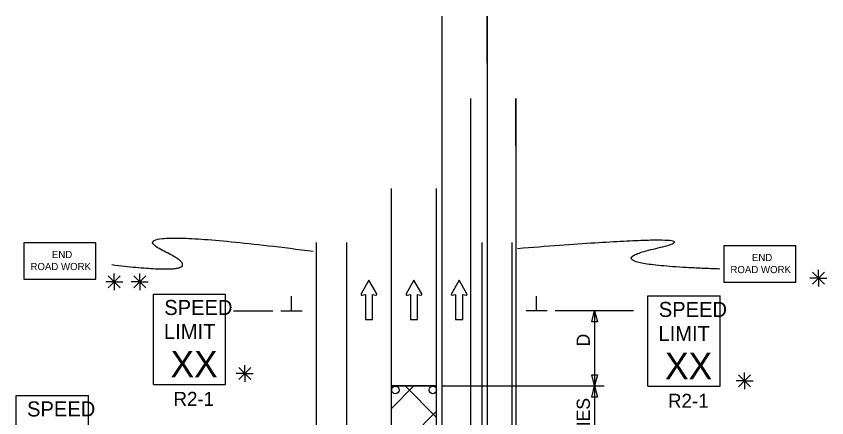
# Model space of a CAD drawing. Extents: x 16480 to 18482, y 7002 to 8333.
# Drawn here: x 16754.4 to 17185.3, y 8119.6 to 8333.1 of the extents above; entities that cross this region are included whole.
import ezdxf

# ---------------------------------------------------------------- set-up
doc = ezdxf.new("R2010")
doc.units = 0
for name, color, linetype in [('ALI_LEGAL_EX', 7, 'Continuous'), ('MT_SCRATCH_LEVEL_E', 7, 'Continuous'), ('PAVT_EDGE_EX', 7, 'Continuous'), ('TRAFFIC_SIGNS_PR', 7, 'Continuous'), ('TYPICAL_TEXT_DIMEN_PR', 7, 'Continuous')]:
    doc.layers.add(name, color=color, linetype=linetype)

msp = doc.modelspace()

# ---------------------------------------------------------------- linework, layer by layer
at = {"layer": 'ALI_LEGAL_EX'}
for p, q in [((16980.68, 8333.08), (16980.68, 7514.94)), ((17004.68, 8333.08), (17004.68, 7514.94)), ((16995.95, 8289.26), (16995.95, 7471.12)), ((17019.95, 8289.26), (17019.95, 7471.12)), ((16953.87, 7620.35), (16953.87, 8241.48)), ((16977.87, 7620.35), (16977.87, 8241.48))]:
    msp.add_line(p, q, dxfattribs=at)
for points in [[(17004.68, 8308.08), (17004.68, 8333.08)], [(17019.95, 8264.26), (17019.95, 8289.26)], [(16953.87, 8175.35), (16953.87, 8200.34)], [(16977.87, 8175.35), (16977.87, 8200.34)]]:
    msp.add_lwpolyline(points, dxfattribs=at)
at = {"layer": 'MT_SCRATCH_LEVEL_E'}
for p, q in [((16941.87, 8192.71), (16937.75, 8185.47)), ((16946.01, 8185.47), (16941.87, 8192.71)), ((16965.77, 8192.71), (16961.66, 8185.47)), ((16969.92, 8185.47), (16965.77, 8192.71)), ((16989.82, 8192.71), (16985.71, 8185.47)), ((16993.97, 8185.47), (16989.82, 8192.71)), ((16938.24, 8184.79), (16940.01, 8185.1)), ((16940.01, 8185.1), (16940.01, 8171.85)), ((16943.76, 8171.85), (16943.76, 8185.1)), ((16943.76, 8185.1), (16945.53, 8184.79)), ((16962.14, 8184.79), (16963.92, 8185.1)), ((16963.92, 8185.1), (16963.92, 8171.85)), ((16967.66, 8171.85), (16967.66, 8185.1)), ((16967.66, 8185.1), (16969.44, 8184.79)), ((16986.19, 8184.79), (16987.97, 8185.1)), ((16987.97, 8185.1), (16987.97, 8171.85)), ((16991.71, 8171.85), (16991.71, 8185.1)), ((16991.71, 8185.1), (16993.49, 8184.79)), ((16940.01, 8171.85), (16943.76, 8171.85)), ((16963.92, 8171.85), (16967.66, 8171.85)), ((16987.97, 8171.85), (16991.71, 8171.85))]:
    msp.add_line(p, q, dxfattribs=at)
for centre, start, end in [((16938.16, 8185.25), 150.4248, 279.9638), ((16945.6, 8185.25), 260.0362, 29.7731), ((16962.07, 8185.25), 150.4248, 279.9638), ((16969.51, 8185.25), 260.0362, 29.7731), ((16986.12, 8185.25), 150.4248, 279.9638), ((16993.56, 8185.25), 260.0362, 29.7731)]:
    msp.add_arc(centre, 0.463, start, end, dxfattribs=at)
at = {"layer": 'PAVT_EDGE_EX'}
for p, q in [((16913.87, 8212.75), (16913.87, 7461.39)), ((16929.87, 8212.75), (16929.87, 7461.39)), ((17001.87, 8212.75), (17001.87, 7461.39)), ((17017.87, 8212.75), (17017.87, 7461.39)), ((16977.87, 8136.53), (16953.87, 8136.53)), ((16953.87, 8136.53), (16977.87, 8136.53)), ((16953.87, 8136.53), (16977.87, 8136.53)), ((16953.87, 8124.62), (16965.77, 8136.53)), ((16977.87, 8119.72), (16961.06, 8136.53)), ((16953.87, 8099.17), (16977.87, 8123.17))]:
    msp.add_line(p, q, dxfattribs=at)
at = {"layer": 'TRAFFIC_SIGNS_PR'}
for p, q in [((16827.3, 8185.4), (16865.7, 8185.4)), ((16827.3, 8137.4), (16827.3, 8185.4)), ((16865.7, 8137.4), (16865.7, 8185.4)), ((17090.18, 8184.37), (17128.58, 8184.37)), ((17090.18, 8136.37), (17090.18, 8184.37)), ((17128.58, 8136.37), (17128.58, 8184.37)), ((16827.3, 8137.4), (16865.7, 8137.4)), ((17090.18, 8136.37), (17128.58, 8136.37)), ((16754.36, 8131.47), (16792.76, 8131.47)), ((16754.36, 8083.47), (16754.36, 8131.47)), ((16792.76, 8083.47), (16792.76, 8131.47))]:
    msp.add_line(p, q, dxfattribs=at)
for points in [[(16758.34, 8193.37), (16796.74, 8193.37), (16796.74, 8212.57), (16758.34, 8212.57)], [(17130.46, 8191.77), (17168.85, 8191.77), (17168.85, 8210.97), (17130.46, 8210.97)]]:
    msp.add_lwpolyline(points, close=True, dxfattribs=at)
for centre in [(16955.97, 8134.41), (16975.84, 8134.41)]:
    msp.add_circle(centre, 2, dxfattribs=at)
for points in [[(16805.28, 8201.02), (16862.04, 8194.06), (16804.04, 8222.17), (16912.21, 8208.18)], [(17128.36, 8198.71), (17056.34, 8201), (17132.86, 8218.41), (17020.93, 8209.49)]]:
    msp.add_open_spline(points, degree=2, dxfattribs=at)
at = {"layer": 'TYPICAL_TEXT_DIMEN_PR'}
for p, q in [((16806.51, 8191.95), (16806.51, 8196.4)), ((16820.02, 8191.95), (16820.02, 8196.4)), ((17183.98, 8197.08), (17177.6, 8190.7)), ((17177.61, 8197.08), (17183.98, 8190.7)), ((17180.79, 8193.89), (17180.79, 8198.35)), ((16806.51, 8191.95), (16801.98, 8191.95)), ((16803.33, 8195.14), (16809.7, 8188.76)), ((16809.7, 8195.14), (16803.33, 8188.76)), ((16806.51, 8191.95), (16809.7, 8191.95)), ((16806.51, 8191.95), (16810.99, 8191.95)), ((16806.51, 8191.95), (16806.51, 8187.45)), ((16820.02, 8191.95), (16815.49, 8191.95)), ((16816.83, 8195.14), (16823.21, 8188.76)), ((16823.21, 8195.14), (16816.83, 8188.76)), ((16820.02, 8191.95), (16823.21, 8191.95)), ((16820.02, 8191.95), (16824.5, 8191.95)), ((16820.02, 8191.95), (16820.02, 8187.45)), ((17180.79, 8193.89), (17176.26, 8193.89)), ((17180.79, 8193.89), (17183.98, 8193.89)), ((17180.79, 8193.89), (17185.27, 8193.89)), ((17180.79, 8193.89), (17180.79, 8189.39)), ((16900.74, 8176.53), (16900.74, 8184.31)), ((16900.74, 8176.53), (16900.74, 8184.31)), ((17030.99, 8176.53), (17030.99, 8184.31)), ((16869.89, 8176.53), (16890.87, 8176.53)), ((16878.29, 8176.53), (16890.87, 8176.53)), ((16895.12, 8176.53), (16906.37, 8176.53)), ((16895.12, 8176.53), (16906.37, 8176.53)), ((17036.62, 8176.53), (17025.37, 8176.53)), ((17082.51, 8176.53), (17040.87, 8176.53)), ((17060.3, 8170.66), (17061.87, 8176.53)), ((17061.87, 8176.53), (17063.44, 8170.66)), ((17061.87, 8176.53), (17061.87, 8136.53)), ((17061.87, 8170.66), (17060.3, 8170.66)), ((17063.44, 8170.66), (17061.87, 8170.66)), ((16872.69, 8146.38), (16879.06, 8140)), ((16879.06, 8146.38), (16872.69, 8140)), ((16875.87, 8143.19), (16875.87, 8147.65)), ((16875.87, 8143.19), (16871.34, 8143.19)), ((16875.87, 8143.19), (16879.06, 8143.19)), ((16875.87, 8143.19), (16880.35, 8143.19)), ((16875.87, 8143.19), (16875.87, 8138.69)), ((17061.87, 8136.53), (17060.3, 8142.39)), ((17060.3, 8142.39), (17061.87, 8142.39)), ((17061.87, 8142.39), (17063.44, 8142.39)), ((17063.44, 8142.39), (17061.87, 8136.53)), ((17138.4, 8142.47), (17144.78, 8136.09)), ((17144.78, 8142.47), (17138.4, 8136.09)), ((17141.59, 8139.28), (17141.59, 8143.74)), ((16980.8, 8136.53), (17066.87, 8136.53)), ((17060.3, 8130.66), (17061.87, 8136.53)), ((17061.87, 8136.53), (17061.87, 8022.8)), ((17061.87, 8136.53), (17063.44, 8130.66)), ((17141.59, 8139.28), (17137.06, 8139.28)), ((17141.59, 8139.28), (17144.78, 8139.28)), ((17141.59, 8139.28), (17146.07, 8139.28)), ((17141.59, 8139.28), (17141.59, 8134.78)), ((17061.87, 8130.66), (17060.3, 8130.66)), ((17063.44, 8130.66), (17061.87, 8130.66))]:
    msp.add_line(p, q, dxfattribs=at)

# ---------------------------------------------------------------- texts
at = {"layer": 'TRAFFIC_SIGNS_PR'}
for s, height, p in [('END', 3.831, (16773.34, 8204.5)), ('END', 3.831, (17145.46, 8202.9)), ('ROAD WORK', 3.831, (16761.95, 8198.12)), ('ROAD WORK', 3.831, (17134.06, 8196.51)), ('SPEED', 8, (16833.07, 8174.26)), ('SPEED', 8, (17095.95, 8173.23)), ('LIMIT', 8, (16832.91, 8161.46)), ('LIMIT', 8, (17095.79, 8160.43)), ('XX', 14.031, (16836.41, 8141.16)), ('XX', 14.031, (17099.29, 8140.13)), ('R2-1', 7.44, (16837.98, 8125.96)), ('R2-1', 7.44, (17100.86, 8124.93)), ('SPEED', 8, (16760.13, 8120.33))]:
    msp.add_text(s, height=height, dxfattribs=at).set_placement(p)
at = {"layer": 'TYPICAL_TEXT_DIMEN_PR'}
for s, p in [('D', (17059.31, 8157.5)), ('WORK AREA VARIES', (17059.31, 8036.02))]:
    msp.add_text(s, height=7, rotation=90, dxfattribs=at).set_placement(p)

doc.saveas('drawing.dxf')
